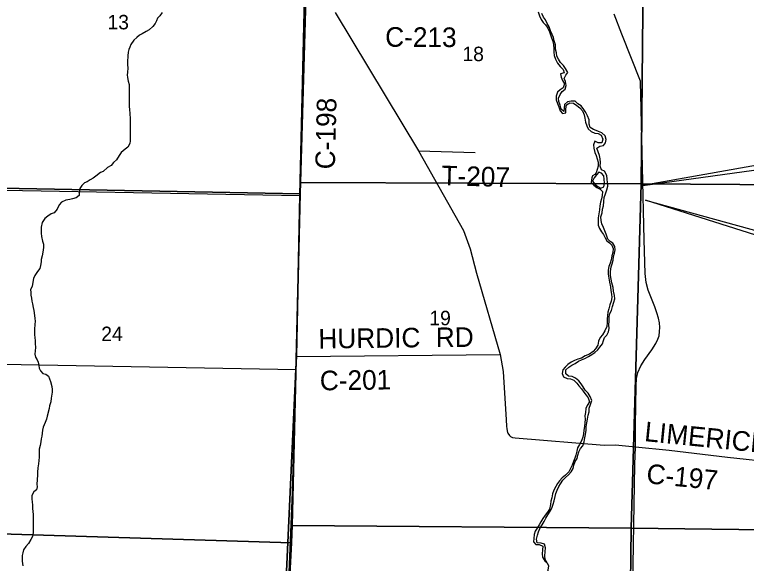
# Model space of a CAD drawing. Extents: x 36.7 to 70.7, y 0 to 22.
# Drawn here: x 40.424 to 42.544, y 15.816 to 17.404 of the extents above; entities that cross this region are included whole.
import ezdxf

# ---------------------------------------------------------------- set-up
doc = ezdxf.new("R2010")
doc.units = 0
for name, color, linetype in [('GM_X_County_Road', 7, 'Continuous'), ('GM_X_County_Road_Text', 7, 'Continuous'), ('GM_X_Minor_River', 7, 'Continuous'), ('GM_X_Section', 7, 'Continuous'), ('GM_X_Section_Text', 7, 'Continuous'), ('GM_X_State_Route', 7, 'Continuous'), ('GM_X_Township_Road', 7, 'Continuous'), ('GM_X_Township_Road_Text', 7, 'Continuous'), ('SH_Text', 7, 'Continuous')]:
    doc.layers.add(name, color=color, linetype=linetype)

msp = doc.modelspace()

# ---------------------------------------------------------------- linework, layer by layer
at = {"layer": 'GM_X_County_Road'}
for p, q in [((41.2501, 16.8809), (41.2664, 17.5366)), ((41.2411, 16.4146), (41.2501, 16.8809)), ((41.2394, 16.377), (41.2411, 16.4146)), ((41.2411, 16.4146), (41.8308, 16.4207))]:
    msp.add_line(p, q, dxfattribs=at)
for points in [[(41.3531, 17.4104), (41.5942, 17.0098), (41.7249, 16.7795), (41.7442, 16.7267), (41.7621, 16.6558), (41.8308, 16.4207)], [(41.8308, 16.4207), (41.8395, 16.3708), (41.8483, 16.2309), (41.8491, 16.2134), (41.8497, 16.205), (41.8522, 16.1943), (41.8529, 16.1924), (41.8574, 16.1859), (41.861, 16.183), (41.866, 16.1801), (41.874, 16.1788), (42.1318, 16.1575), (42.1649, 16.1587), (42.2224, 16.1536)], [(39.2718, 16.4014), (39.5265, 16.4061), (40.1763, 16.3968), (41.2394, 16.377)], [(42.2224, 16.1536), (42.32, 16.1431), (42.4892, 16.1233), (42.6333, 16.1077), (42.7073, 16.1297), (42.9675, 16.211), (43.2265, 16.2915), (43.4871, 16.3698), (43.587, 16.3971), (43.7291, 16.4012), (43.9799, 16.3965), (44.2264, 16.4016)], [(41.1844, 14.9819), (41.2095, 15.5574), (41.2295, 16.0217), (41.2394, 16.377)]]:
    msp.add_lwpolyline(points, dxfattribs=at)
at = {"layer": 'GM_X_Minor_River'}
for points in [[(40.8515, 17.4104), (40.8446, 17.4014), (40.838, 17.3942), (40.8353, 17.3867), (40.8314, 17.3787), (40.8249, 17.3697), (40.8141, 17.36), (40.805, 17.3555), (40.7935, 17.3488), (40.7863, 17.3454), (40.7778, 17.3379), (40.7698, 17.3308), (40.7609, 17.318), (40.7574, 17.3105), (40.7547, 17.3033), (40.7531, 17.2961), (40.7518, 17.2855), (40.7513, 17.268), (40.7515, 17.2593), (40.7522, 17.2505), (40.7513, 17.2373), (40.7501, 17.2301), (40.7511, 17.2228), (40.7533, 17.2114), (40.7558, 17.2023), (40.7556, 17.1799), (40.7562, 17.1678), (40.7556, 17.1537), (40.7556, 17.1461), (40.7562, 17.1389), (40.7573, 17.1298), (40.7579, 17.118), (40.7585, 17.1028)], [(41.9409, 17.4125), (41.9444, 17.401), (41.9498, 17.3902), (41.9548, 17.3821), (41.9618, 17.3747), (41.9684, 17.365), (41.9734, 17.3546), (41.9787, 17.3401), (41.9819, 17.3293), (41.985, 17.3182), (41.9858, 17.3057)], [(42.1415, 16.7569), (42.1381, 16.7684), (42.1338, 16.7788), (42.1303, 16.7884), (42.1256, 16.7984), (42.1236, 16.8087), (42.1227, 16.8186), (42.1257, 16.831), (42.1275, 16.8416), (42.1297, 16.8511), (42.1312, 16.8635), (42.1322, 16.8749), (42.1355, 16.8858), (42.1393, 16.8975), (42.1422, 16.908), (42.1417, 16.9183), (42.1409, 16.9282), (42.1393, 16.9389), (42.1331, 16.9508), (42.1238, 16.9549), (42.1199, 16.9656), (42.1209, 16.9762), (42.1205, 16.9869), (42.1184, 16.9964), (42.1149, 17.0068), (42.1111, 17.0183), (42.1192, 17.0241), (42.1298, 17.0253), (42.1361, 17.0331), (42.1375, 17.043), (42.1344, 17.0537), (42.1252, 17.0627), (42.1156, 17.0663), (42.1083, 17.0691), (42.1008, 17.0717), (42.0915, 17.078), (42.0883, 17.0876), (42.0883, 17.1001), (42.0836, 17.1116), (42.079, 17.1209), (42.0732, 17.1302), (42.0651, 17.1403), (42.0561, 17.1462), (42.0476, 17.1544), (42.0363, 17.154), (42.026, 17.152), (42.017, 17.1442), (42.0156, 17.134), (42.015, 17.1242), (42.0076, 17.1304), (42.0041, 17.1419), (42.001, 17.153), (42.0001, 17.1625), (42.0046, 17.1734), (42.0105, 17.182), (42.0186, 17.189), (42.0216, 17.1992), (42.0203, 17.2106), (42.0164, 17.2198), (42.0209, 17.2296), (42.0264, 17.2374), (42.0199, 17.2489), (42.014, 17.2571), (42.0059, 17.2657), (41.9993, 17.2753), (41.995, 17.2842), (41.9938, 17.2937), (41.9914, 17.3048), (41.9906, 17.3166), (41.9875, 17.3288), (41.9855, 17.3383), (41.9816, 17.3472), (41.9769, 17.3579), (41.9727, 17.3691), (41.9669, 17.3791), (41.9619, 17.3895), (41.9564, 17.3972), (41.951, 17.4076)], [(41.9858, 17.3057), (41.9866, 17.2954), (41.9875, 17.2859), (41.9906, 17.2756), (41.9971, 17.2636), (42.0041, 17.2539), (42.013, 17.2461), (42.0157, 17.2358), (42.0054, 17.2334), (42.0074, 17.2235), (42.0117, 17.2142), (42.0168, 17.2042), (42.013, 17.1929), (42.0041, 17.1863), (41.9964, 17.1797), (41.9927, 17.1681), (41.9931, 17.1574), (41.997, 17.1471), (42.0005, 17.1375), (42.004, 17.1264), (42.0114, 17.1178), (42.0206, 17.1202), (42.0212, 17.1312), (42.0227, 17.1429), (42.0327, 17.1487), (42.0429, 17.1481), (42.053, 17.1413), (42.0611, 17.1343), (42.0689, 17.1257), (42.0739, 17.1146), (42.0759, 17.105), (42.0782, 17.0936), (42.0813, 17.0825), (42.0856, 17.0736), (42.0942, 17.0662), (42.1047, 17.0617), (42.1145, 17.0599), (42.1234, 17.0551), (42.1281, 17.0436), (42.1251, 17.0331), (42.1145, 17.0333), (42.1052, 17.0382), (42.1015, 17.0276), (42.102, 17.0181), (42.105, 17.0055), (42.109, 16.9967), (42.1121, 16.9871), (42.1141, 16.9772), (42.1142, 16.9661), (42.1087, 16.9462), (42.1045, 16.9421), (42.0983, 16.9374), (42.0966, 16.9317), (42.0947, 16.9185), (42.1017, 16.9107), (42.1103, 16.9044), (42.1204, 16.8992), (42.1274, 16.8925), (42.1259, 16.8812), (42.1238, 16.8713), (42.1216, 16.8612), (42.1194, 16.851), (42.118, 16.8392), (42.1165, 16.8279), (42.1147, 16.8162), (42.1141, 16.8063), (42.1145, 16.7945), (42.1184, 16.7853), (42.1246, 16.7753), (42.1301, 16.7675), (42.1344, 16.7583), (42.1398, 16.7494), (42.1472, 16.7435)], [(40.7585, 17.1028), (40.7588, 17.0945), (40.759, 17.08), (40.7589, 17.0706), (40.7591, 17.0561), (40.759, 17.0482), (40.7585, 17.0394), (40.758, 17.0315), (40.7522, 17.0209), (40.7446, 17.0153), (40.7327, 17.0052), (40.7269, 16.9965), (40.7196, 16.9841), (40.7104, 16.9762), (40.7042, 16.9679), (40.6935, 16.9619), (40.6805, 16.9507), (40.6732, 16.947), (40.6591, 16.9365), (40.6518, 16.9313), (40.6434, 16.926), (40.6343, 16.9201), (40.627, 16.9171), (40.619, 16.9096), (40.6132, 16.9013), (40.6115, 16.8899), (40.6107, 16.8808), (40.6026, 16.8741), (40.592, 16.8708), (40.584, 16.8694), (40.5726, 16.8672), (40.5604, 16.8613), (40.5535, 16.8541), (40.5476, 16.8413), (40.5388, 16.8304), (40.53, 16.8274), (40.5201, 16.8211), (40.5117, 16.8147), (40.5039, 16.803), (40.5008, 16.7887), (40.5006, 16.7716), (40.5016, 16.7625), (40.5045, 16.7484), (40.5074, 16.74), (40.5081, 16.7316), (40.5068, 16.7225), (40.5036, 16.7066), (40.5012, 16.696), (40.5007, 16.6884), (40.4987, 16.6778), (40.4967, 16.6691), (40.4902, 16.6608), (40.4828, 16.6488), (40.479, 16.6405), (40.4769, 16.6302), (40.4745, 16.617), (40.4706, 16.6083), (40.4709, 16.5996), (40.4712, 16.5923), (40.473, 16.5832), (40.474, 16.5752), (40.4762, 16.5676), (40.4776, 16.5566), (40.4802, 16.5475), (40.4815, 16.5334), (40.483, 16.525), (40.4836, 16.5167), (40.4831, 16.5072), (40.4818, 16.4939), (40.4817, 16.4848), (40.4813, 16.4772), (40.4823, 16.4696), (40.4834, 16.4601), (40.484, 16.4525), (40.4847, 16.4411), (40.4838, 16.4309), (40.4829, 16.421), (40.4843, 16.4123), (40.4892, 16.405), (40.4925, 16.3978), (40.4939, 16.3883), (40.4954, 16.381), (40.4994, 16.3734), (40.5054, 16.3657), (40.5145, 16.3637), (40.5224, 16.358), (40.5283, 16.3423), (40.5315, 16.3283), (40.5326, 16.3195), (40.5333, 16.3115), (40.53, 16.2937), (40.5288, 16.2831), (40.5256, 16.2718), (40.524, 16.2642), (40.5184, 16.2422), (40.5161, 16.2335), (40.5122, 16.2237), (40.5071, 16.2101), (40.5051, 16.201), (40.5026, 16.1843), (40.501, 16.176)], [(42.1168, 16.9482), (42.1101, 16.9404), (42.1027, 16.9315), (42.0979, 16.9222), (42.1045, 16.914), (42.1137, 16.9069), (42.122, 16.9021), (42.1312, 16.9057), (42.1333, 16.9163)], [(42.1333, 16.9163), (42.1318, 16.9277), (42.1309, 16.938), (42.1239, 16.9458), (42.1168, 16.9482)], [(41.9671, 15.8174), (41.9613, 15.8271), (41.9601, 15.8374), (41.9615, 15.8495), (41.9618, 15.8605), (41.9591, 15.8716), (41.9493, 15.8745), (41.9379, 15.8752), (41.9356, 15.8863), (41.9385, 15.8972), (41.9418, 15.9074), (41.9467, 15.9186), (41.9519, 15.9272), (41.9578, 15.9369), (41.9634, 15.9466), (41.969, 15.9567), (41.9757, 15.9672), (41.9801, 15.9758), (41.9838, 15.9867), (41.9875, 15.9972), (41.9897, 16.0089), (41.9919, 16.0184), (41.9955, 16.0281), (42.0007, 16.0379), (42.0059, 16.0465), (42.0126, 16.0565), (42.0204, 16.0643), (42.029, 16.072), (42.0368, 16.0809), (42.042, 16.0907), (42.0445, 16.1001), (42.0475, 16.111), (42.0537, 16.1192), (42.0555, 16.1294), (42.0581, 16.1388), (42.0633, 16.1482), (42.0703, 16.1559), (42.0736, 16.1676), (42.0762, 16.1789), (42.078, 16.1888), (42.0795, 16.2013), (42.0801, 16.2111), (42.0816, 16.2225), (42.0834, 16.2334), (42.086, 16.2444), (42.0881, 16.2549), (42.0888, 16.2652), (42.0921, 16.2753), (42.0958, 16.2874), (42.0912, 16.2985), (42.0854, 16.3082), (42.0773, 16.3171), (42.0711, 16.3264), (42.0649, 16.3357), (42.0587, 16.3446), (42.0491, 16.3521), (42.0397, 16.3565), (42.0287, 16.358), (42.021, 16.3646), (42.0213, 16.3764), (42.0294, 16.3834), (42.0383, 16.3896), (42.0475, 16.3943), (42.0572, 16.4008), (42.0664, 16.4048), (42.076, 16.409), (42.0868, 16.4145), (42.0964, 16.4203), (42.1045, 16.4265), (42.1135, 16.4338), (42.1197, 16.4416), (42.1268, 16.4513), (42.1301, 16.4607), (42.133, 16.4698), (42.14, 16.4768), (42.1448, 16.4858), (42.1466, 16.496), (42.1457, 16.5062), (42.146, 16.5169), (42.1467, 16.5279), (42.1473, 16.5373), (42.1533, 16.5482), (42.1563, 16.5591), (42.1604, 16.5719), (42.1626, 16.5813), (42.1617, 16.5916), (42.1594, 16.6038), (42.1582, 16.6149), (42.154, 16.6283), (42.152, 16.6382), (42.1504, 16.6493), (42.1499, 16.6607), (42.1526, 16.6739), (42.1551, 16.6833), (42.158, 16.6935), (42.1594, 16.7041), (42.162, 16.7135), (42.1641, 16.7237), (42.1633, 16.7332), (42.1575, 16.7432), (42.1493, 16.748)], [(42.1493, 16.748), (42.1422, 16.7547), (42.1415, 16.7569)], [(42.1472, 16.7435), (42.1546, 16.7368), (42.1578, 16.7273), (42.1571, 16.7155), (42.1546, 16.7061), (42.1524, 16.6948), (42.1494, 16.6846), (42.1458, 16.6756), (42.1436, 16.665), (42.1433, 16.6529), (42.1452, 16.641), (42.1472, 16.63), (42.1499, 16.6162), (42.1511, 16.6056), (42.1531, 16.5949), (42.154, 16.5854), (42.1522, 16.5752), (42.1481, 16.5639), (42.1451, 16.553), (42.143, 16.5431), (42.1412, 16.5337), (42.1405, 16.5231), (42.1406, 16.5132), (42.1392, 16.5015), (42.1343, 16.4887), (42.1272, 16.4779), (42.1205, 16.4693), (42.1156, 16.4588), (42.1134, 16.4471), (42.1071, 16.4367), (42.0997, 16.4289), (42.0896, 16.4216), (42.0773, 16.4166), (42.0662, 16.4101), (42.0558, 16.4069), (42.0463, 16.4034), (42.0363, 16.3984), (42.027, 16.3914), (42.0188, 16.384), (42.0125, 16.3759), (42.0104, 16.3653), (42.0139, 16.3561), (42.0248, 16.3512), (42.0342, 16.3498), (42.0443, 16.3458), (42.0532, 16.3372), (42.0587, 16.3294), (42.0664, 16.3208), (42.073, 16.3112), (42.08, 16.303), (42.0854, 16.2953), (42.0893, 16.283), (42.0826, 16.2733), (42.0793, 16.2643), (42.0775, 16.2526), (42.0761, 16.2431), (42.0766, 16.2332), (42.0759, 16.2226), (42.0752, 16.2116), (42.073, 16.2011), (42.0716, 16.1908), (42.0698, 16.181), (42.0661, 16.1701), (42.0609, 16.16), (42.0546, 16.1503), (42.0524, 16.1409), (42.0502, 16.1295), (42.047, 16.1205), (42.0433, 16.1104), (42.0392, 16.0998), (42.0344, 16.0905), (42.0292, 16.0808), (42.0198, 16.0715), (42.0105, 16.0638), (42.0027, 16.0545), (41.9968, 16.0467), (41.992, 16.0381), (41.986, 16.0273), (41.9827, 16.0167), (41.9802, 16.0058), (41.9772, 15.9956), (41.9766, 15.9858), (41.9736, 15.9729), (41.968, 15.9643), (41.9606, 15.9551), (41.9539, 15.9454), (41.9487, 15.936), (41.9432, 15.9278), (41.9376, 15.9181), (41.9316, 15.9088), (41.9295, 15.899), (41.928, 15.8876), (41.927, 15.8778), (41.934, 15.8704), (41.9435, 15.8701), (41.954, 15.866), (41.9533, 15.8554), (41.9519, 15.8429), (41.9535, 15.8334), (41.9597, 15.8233), (41.9671, 15.8174)], [(40.501, 16.176), (40.4998, 16.168), (40.4977, 16.1567), (40.4957, 16.1461), (40.4952, 16.1313), (40.4951, 16.1233), (40.493, 16.1043), (40.4917, 16.0926), (40.4904, 16.0797), (40.4903, 16.0725), (40.4898, 16.0577), (40.4889, 16.0455), (40.4892, 16.0376), (40.4876, 16.0289), (40.4795, 16.0225), (40.4737, 16.0123), (40.4743, 16.0013), (40.4754, 15.9941), (40.4757, 15.9842), (40.4763, 15.9747), (40.478, 15.9568), (40.4783, 15.947), (40.4779, 15.9109), (40.4782, 15.9037), (40.4762, 15.8938), (40.4711, 15.8848), (40.4645, 15.8735), (40.4565, 15.8648), (40.4503, 15.8554), (40.4479, 15.8459), (40.4459, 15.8384), (40.4455, 15.8304), (40.4461, 15.8224), (40.4479, 15.8083)], [(41.9671, 15.8174), (41.971, 15.8086), (41.9692, 15.7965), (41.9687, 15.7938), (41.9652, 15.7892)]]:
    msp.add_lwpolyline(points, dxfattribs=at)
at = {"layer": 'GM_X_Section'}
for points in [[(42.2487, 17.912), (42.2388, 16.9146), (41.2523, 16.9188), (41.2806, 17.8858), (41.2819, 17.9105)], [(43.2576, 17.9081), (43.2397, 16.908), (42.2388, 16.9146), (42.2487, 17.912)], [(41.2806, 17.8858), (41.2523, 16.9188), (41.2509, 16.8855), (40.1819, 16.9057), (40.1915, 17.9066)], [(42.2388, 16.9146), (42.2098, 15.9172), (41.2283, 15.9252), (41.2509, 16.8855), (41.2523, 16.9188)], [(41.2509, 16.8855), (41.2283, 15.9252), (41.2265, 15.8756), (40.1632, 15.9076), (40.1819, 16.9057)], [(43.2397, 16.908), (43.2232, 15.9056), (42.2098, 15.9172), (42.2388, 16.9146)], [(42.2098, 15.9172), (42.199, 14.9604), (41.1785, 14.9796), (41.2265, 15.8756), (41.2283, 15.9252)], [(41.2265, 15.8756), (41.1785, 14.9796), (41.1776, 14.9705), (40.1892, 14.9717), (40.1834, 15.4299), (40.1588, 15.7484), (40.1632, 15.9076)], [(43.2232, 15.9056), (43.2077, 14.934), (42.199, 14.9604), (42.2098, 15.9172)]]:
    msp.add_lwpolyline(points, close=True, dxfattribs=at)
at = {"layer": 'GM_X_State_Route'}
msp.add_lwpolyline([(42.2144, 15.6947), (42.2208, 16.1022), (42.2224, 16.1536), (42.223, 16.2146), (42.2243, 16.3307), (42.2255, 16.3509), (42.2297, 16.3679), (42.2379, 16.3876), (42.2498, 16.4056), (42.2703, 16.434), (42.2819, 16.4522), (42.2878, 16.4644), (42.2909, 16.4748), (42.2926, 16.4868), (42.2931, 16.4987), (42.2919, 16.5125), (42.289, 16.5259), (42.2846, 16.5412), (42.279, 16.5585), (42.2593, 16.6071), (42.2535, 16.6289), (42.2503, 16.6554), (42.2474, 16.7524), (42.2377, 17.1734), (42.2374, 17.2073), (42.2371, 17.2118), (42.183, 17.3482), (42.1609, 17.4056)], dxfattribs=at)
at = {"layer": 'GM_X_Township_Road'}
msp.add_line((41.5942, 17.0098), (41.7582, 17.0053), dxfattribs=at)
for points in [[(41.1522, 14.4699), (41.174, 14.9671), (41.1745, 14.977), (41.2392, 16.3776), (41.2409, 16.4152), (41.2499, 16.8815), (41.2661, 17.5372), (41.3022, 18.3874), (41.3025, 18.3936), (41.3037, 18.4227), (41.344, 19.4017), (41.3441, 19.4051), (41.3623, 19.8162), (40.8614, 19.8261), (40.8514, 19.8263), (40.7997, 19.8273), (40.7924, 19.8275), (40.7387, 19.8285), (40.7272, 19.8287), (40.1721, 19.8397)], [(41.2661, 17.5372), (41.2499, 16.8815), (41.2409, 16.4152), (41.2392, 16.3776), (41.1745, 14.977), (41.174, 14.9671), (41.1522, 14.4699)], [(39.4251, 16.9015), (40.1787, 16.9), (41.2501, 16.8809)]]:
    msp.add_lwpolyline(points, dxfattribs=at)
at = {"layer": 'SH_Text'}
for points in [[(47.1799, 17.7861), (42.2435, 16.9102), (47.1799, 17.5925)], [(42.2513, 16.8669), (47.0528, 15.5458), (47.0528, 15.3449)]]:
    msp.add_lwpolyline(points, close=True, dxfattribs=at)

# ---------------------------------------------------------------- texts
at = {"layer": 'GM_X_County_Road_Text'}
for s, rotation, p in [('C-213', 359.7247, (41.4975, 17.3115)), ('C-198', 88.6237, (41.3517, 16.9561)), ('HURDIC', 0.7187, (41.3044, 16.4376)), ('RD', 0.4936, (41.6444, 16.4417)), ('C-201', 0.8264, (41.3086, 16.3165)), ('LIMERICK', 354.3034, (42.2468, 16.1699)), ('C-197', 354.4817, (42.2526, 16.0478))]:
    msp.add_text(s, height=0.05682, rotation=rotation, dxfattribs=at).set_placement(p)
at = {"layer": 'GM_X_Section_Text'}
for s, p in [('13', (40.693, 17.3619)), ('18', (41.7213, 17.2698)), ('19', (41.6255, 16.5052)), ('24', (40.6751, 16.4593))]:
    msp.add_text(s, height=0.04186, rotation=0, dxfattribs=at).set_placement(p)
at = {"layer": 'GM_X_Township_Road_Text'}
msp.add_text('T-207', height=0.05682, rotation=358.4309, dxfattribs=at).set_placement((41.6599, 16.9106))

doc.saveas('drawing.dxf')
